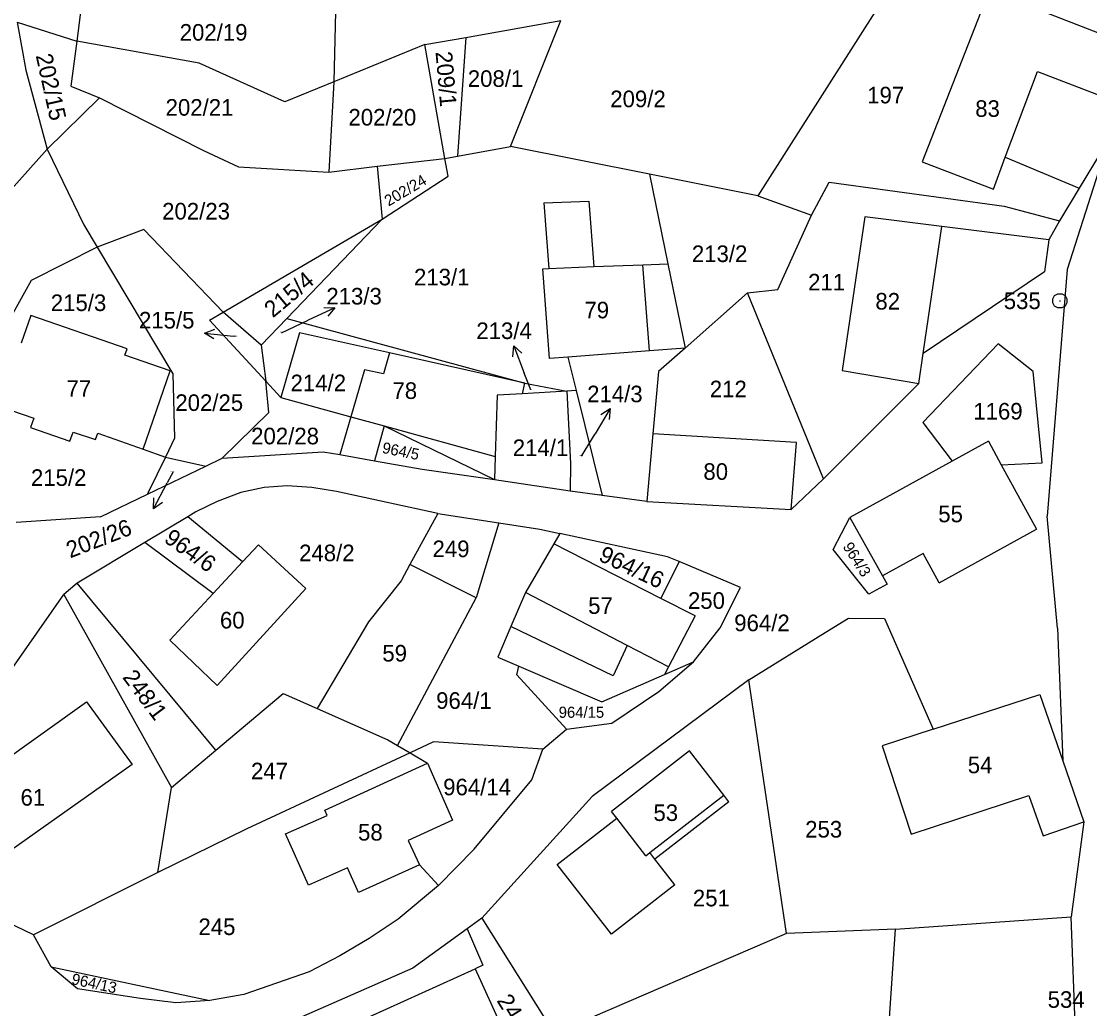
# Model space of a CAD drawing. Extents: x -593358 to -590116, y -1072518 to -1068420.
# Drawn here: x -591903.9 to -591794.4, y -1071067.8 to -1070966.6 of the extents above; entities that cross this region are included whole.
import ezdxf

# ---------------------------------------------------------------- set-up
doc = ezdxf.new("R2010")
doc.units = 0
for name, color, linetype in [('Parcela KN', 7, 'Continuous'), ('Parcela ZE', 7, 'Continuous'), ('Parcelní číslo', 7, 'Continuous'), ('Parcelní číslo_stavební', 7, 'Continuous'), ('stavby - vnitřní kresba', 7, 'Continuous'), ('Vrstva 16', 7, 'Continuous'), ('Vrstva 17', 7, 'Continuous'), ('Vrstva 24', 7, 'Continuous')]:
    doc.layers.add(name, color=color, linetype=linetype)

msp = doc.modelspace()

# ---------------------------------------------------------------- linework, layer by layer
at = {"layer": 'Parcela KN'}
for p, q in [((-591812.84, -1070959.98), (-591828.43, -1070984.45)), ((-591804.71, -1070963.4), (-591811.57, -1070980.97)), ((-591804.71, -1070963.4), (-591788.98, -1070969.54)), ((-591904.35, -1070966.66), (-591903.48, -1070971.6)), ((-591858.38, -1070968.23), (-591848.62, -1070966.51)), ((-591853.8, -1070979.4), (-591848.62, -1070966.51)), ((-591862.56, -1070968.97), (-591858.38, -1070968.23)), ((-591858.38, -1070968.23), (-591859.21, -1070980.4)), ((-591860.51, -1070980.64), (-591862.56, -1070968.97)), ((-591903.48, -1070971.6), (-591901.27, -1070979.67)), ((-591859.21, -1070980.4), (-591853.8, -1070979.4)), ((-591839.55, -1070982.24), (-591853.8, -1070979.4)), ((-591792.45, -1070978.67), (-591796.7, -1070992.01)), ((-591792.45, -1070978.67), (-591795.47, -1070983.67)), ((-591910.09, -1070989.49), (-591901.27, -1070979.67)), ((-591901.27, -1070979.67), (-591897.53, -1070987.45)), ((-591860.51, -1070980.64), (-591859.21, -1070980.4)), ((-591860.19, -1070982.46), (-591860.51, -1070980.64)), ((-591804.28, -1070983.77), (-591803.08, -1070980.5)), ((-591803.08, -1070980.5), (-591795.47, -1070983.67)), ((-591811.57, -1070980.97), (-591804.28, -1070983.77)), ((-591866.93, -1070986.84), (-591860.19, -1070982.46)), ((-591839.55, -1070982.24), (-591837.67, -1070991.42)), ((-591828.43, -1070984.45), (-591839.55, -1070982.24)), ((-591822.91, -1070986.45), (-591821.12, -1070983.06)), ((-591821.12, -1070983.06), (-591803.16, -1070985.53)), ((-591795.47, -1070983.67), (-591797.51, -1070987.04)), ((-591850.36, -1070985.18), (-591845.77, -1070985)), ((-591845.77, -1070985), (-591845.24, -1070991.72)), ((-591828.43, -1070984.45), (-591822.91, -1070986.45)), ((-591850.36, -1070985.18), (-591849.87, -1070991.91)), ((-591803.16, -1070985.53), (-591797.51, -1070987.04)), ((-591883.23, -1070996.39), (-591866.93, -1070986.84)), ((-591866.93, -1070986.84), (-591876.7, -1070997.02)), ((-591826.37, -1070994.05), (-591822.91, -1070986.45)), ((-591817.44, -1070986.63), (-591819.77, -1071002.38)), ((-591809.55, -1070987.61), (-591817.44, -1070986.63)), ((-591797.51, -1070987.04), (-591798.61, -1070988.96)), ((-591897.53, -1070987.45), (-591896.16, -1070989.74)), ((-591798.61, -1070988.96), (-591809.55, -1070987.61)), ((-591798.61, -1070988.96), (-591799.04, -1070992.25)), ((-591896.16, -1070989.74), (-591902.93, -1070993.15)), ((-591896.16, -1070989.74), (-591888.41, -1071002.71)), ((-591845.24, -1070991.72), (-591840.2, -1070991.52)), ((-591840.2, -1070991.52), (-591837.67, -1070991.42)), ((-591837.67, -1070991.42), (-591835.89, -1071000.06)), ((-591850.47, -1070991.93), (-591849.87, -1070991.91)), ((-591849.79, -1071001.14), (-591850.47, -1070991.93)), ((-591799.04, -1070992.25), (-591811.48, -1071000.63)), ((-591796.7, -1070992.01), (-591798.76, -1071017.31)), ((-591902.93, -1070993.15), (-591907.76, -1071001.82)), ((-591829.5, -1070994.41), (-591835.89, -1071000.06)), ((-591829.5, -1070994.41), (-591826.37, -1070994.05)), ((-591821.71, -1071013.46), (-591829.5, -1070994.41)), ((-591902.95, -1070996.74), (-591903.96, -1070999.56)), ((-591893.07, -1071000.16), (-591902.95, -1070996.74)), ((-591884.64, -1070997.21), (-591883.23, -1070996.39)), ((-591879.33, -1070999.76), (-591883.23, -1070996.39)), ((-591876.7, -1070997.02), (-591879.33, -1070999.76)), ((-591876.7, -1070997.02), (-591852.32, -1071003.66)), ((-591884.64, -1070997.21), (-591878.88, -1071003.46)), ((-591875.43, -1070998.51), (-591877.34, -1071005.13)), ((-591866.2, -1071000.57), (-591875.43, -1070998.51)), ((-591893.31, -1071000.81), (-591893.07, -1071000.16)), ((-591879.33, -1070999.76), (-591878.88, -1071003.46)), ((-591835.89, -1071000.06), (-591838.61, -1071002.46)), ((-591803.79, -1070999.63), (-591811.5, -1071007.69)), ((-591800.19, -1071002.48), (-591803.79, -1070999.63)), ((-591888.67, -1071002.41), (-591893.31, -1071000.81)), ((-591866.2, -1071000.57), (-591866.82, -1071002.72)), ((-591852.32, -1071003.66), (-591866.2, -1071000.57)), ((-591847.9, -1071000.99), (-591849.79, -1071001.14)), ((-591847.9, -1071000.99), (-591847.04, -1071004.43)), ((-591811.93, -1071003.68), (-591811.48, -1071000.63)), ((-591891.45, -1071010.41), (-591888.67, -1071002.41)), ((-591868.75, -1071002.29), (-591870.14, -1071007.11)), ((-591866.82, -1071002.72), (-591868.75, -1071002.29)), ((-591838.61, -1071002.46), (-591839.19, -1071008.84)), ((-591819.77, -1071002.38), (-591811.93, -1071003.68)), ((-591799.67, -1071007.7), (-591800.19, -1071002.48)), ((-591888.41, -1071002.71), (-591888.22, -1071009.29)), ((-591878.88, -1071003.46), (-591877.34, -1071005.13)), ((-591852.56, -1071004.74), (-591852.32, -1071003.66)), ((-591852.32, -1071003.66), (-591848.01, -1071004.48)), ((-591811.93, -1071003.68), (-591821.71, -1071013.46)), ((-591852.56, -1071004.74), (-591855.14, -1071004.88)), ((-591848.01, -1071004.48), (-591852.56, -1071004.74)), ((-591847.04, -1071004.43), (-591848.01, -1071004.48)), ((-591848.01, -1071004.48), (-591847.62, -1071011.9)), ((-591847.04, -1071004.43), (-591844.37, -1071015.16)), ((-591877.34, -1071005.13), (-591870.14, -1071007.11)), ((-591855.14, -1071004.88), (-591855.34, -1071011.18)), ((-591906.16, -1071006.04), (-591902.64, -1071007.25)), ((-591902.64, -1071007.25), (-591902.99, -1071008.19)), ((-591870.14, -1071007.11), (-591871.27, -1071010.99)), ((-591866.73, -1071008.05), (-591867.73, -1071011.61)), ((-591866.73, -1071008.05), (-591855.42, -1071013.55)), ((-591811.5, -1071007.69), (-591808.52, -1071011.67)), ((-591799.28, -1071011.82), (-591799.67, -1071007.7)), ((-591902.99, -1071008.19), (-591898.95, -1071009.59)), ((-591898.95, -1071009.59), (-591898.61, -1071008.67)), ((-591898.61, -1071008.67), (-591896.34, -1071009.45)), ((-591896.34, -1071009.45), (-591896.08, -1071008.77)), ((-591896.08, -1071008.77), (-591891.45, -1071010.41)), ((-591839.19, -1071008.84), (-591839.82, -1071015.79)), ((-591824.45, -1071009.73), (-591839.19, -1071008.84)), ((-591888.22, -1071009.29), (-591889.15, -1071011.23)), ((-591825, -1071016.62), (-591824.45, -1071009.73)), ((-591804.78, -1071009.62), (-591808.52, -1071011.67)), ((-591804.78, -1071009.62), (-591803.47, -1071012.02)), ((-591891.45, -1071010.41), (-591889.15, -1071011.23)), ((-591889.15, -1071011.23), (-591890.92, -1071014.88)), ((-591885.03, -1071012.17), (-591883.36, -1071011.36)), ((-591883.36, -1071011.36), (-591872.98, -1071010.69)), ((-591872.98, -1071010.69), (-591871.27, -1071010.99)), ((-591871.27, -1071010.99), (-591867.73, -1071011.61)), ((-591855.34, -1071011.18), (-591855.42, -1071013.55)), ((-591891, -1071015.04), (-591885.03, -1071012.17)), ((-591867.73, -1071011.61), (-591862.85, -1071012.47)), ((-591847.62, -1071011.9), (-591847.66, -1071014.68)), ((-591808.52, -1071011.67), (-591819.01, -1071017.43)), ((-591803.47, -1071012.02), (-591799.28, -1071011.82)), ((-591803.47, -1071012.02), (-591799.86, -1071018.63)), ((-591862.85, -1071012.47), (-591855.42, -1071013.55)), ((-591855.42, -1071013.55), (-591847.66, -1071014.68)), ((-591825, -1071016.62), (-591821.71, -1071013.46)), ((-591879.03, -1071014.37), (-591881.42, -1071014.87)), ((-591876.69, -1071014.2), (-591879.03, -1071014.37)), ((-591874.16, -1071014.34), (-591876.69, -1071014.2)), ((-591871.61, -1071014.75), (-591874.16, -1071014.34)), ((-591895.82, -1071017.36), (-591891, -1071015.04)), ((-591890.92, -1071014.88), (-591891, -1071015.04)), ((-591881.42, -1071014.87), (-591883.86, -1071015.78)), ((-591861.24, -1071017.03), (-591871.61, -1071014.75)), ((-591847.66, -1071014.68), (-591844.64, -1071015.12)), ((-591844.37, -1071015.16), (-591844.64, -1071015.12)), ((-591839.82, -1071015.79), (-591844.37, -1071015.16)), ((-591883.86, -1071015.78), (-591886.06, -1071016.86)), ((-591839.82, -1071015.79), (-591825, -1071016.62)), ((-591895.82, -1071017.36), (-591904.48, -1071017.94)), ((-591886.87, -1071017.35), (-591891.27, -1071019.99)), ((-591886.06, -1071016.86), (-591886.87, -1071017.35)), ((-591881.25, -1071021.98), (-591886.87, -1071017.35)), ((-591861.24, -1071017.03), (-591864.1, -1071022.24)), ((-591861.24, -1071017.03), (-591854.99, -1071017.99)), ((-591820.71, -1071020.71), (-591819.01, -1071017.43)), ((-591819.01, -1071017.43), (-591815.65, -1071023.42)), ((-591797.69, -1071028.77), (-591798.76, -1071017.31)), ((-591854.99, -1071017.99), (-591857.3, -1071025.66)), ((-591854.99, -1071017.99), (-591850.78, -1071018.64)), ((-591850.78, -1071018.64), (-591848.72, -1071019.06)), ((-591809.85, -1071024.12), (-591799.86, -1071018.63)), ((-591891.27, -1071019.99), (-591898.22, -1071024.15)), ((-591884.28, -1071025.23), (-591891.27, -1071019.99)), ((-591848.72, -1071019.06), (-591849.35, -1071020.14)), ((-591837.7, -1071021.45), (-591848.72, -1071019.06)), ((-591881.25, -1071021.98), (-591879.62, -1071020.22)), ((-591879.62, -1071020.22), (-591874.77, -1071024.72)), ((-591849.35, -1071020.14), (-591852.25, -1071025.12)), ((-591838.38, -1071025.72), (-591849.35, -1071020.14)), ((-591817.03, -1071025.27), (-591820.71, -1071020.71)), ((-591811.49, -1071021.13), (-591815.65, -1071023.42)), ((-591809.85, -1071024.12), (-591811.49, -1071021.13)), ((-591884.28, -1071025.23), (-591881.25, -1071021.98)), ((-591864.1, -1071022.24), (-591864.99, -1071023.91)), ((-591857.3, -1071025.66), (-591864.1, -1071022.24)), ((-591836.49, -1071021.95), (-591838.38, -1071025.72)), ((-591836.49, -1071021.95), (-591837.7, -1071021.45)), ((-591830.19, -1071024.6), (-591836.49, -1071021.95)), ((-591898.22, -1071024.15), (-591899.57, -1071025.31)), ((-591883.98, -1071041.28), (-591898.22, -1071024.15)), ((-591864.99, -1071023.91), (-591868.33, -1071028.11)), ((-591815.18, -1071024.26), (-591817.03, -1071025.27)), ((-591815.65, -1071023.42), (-591815.18, -1071024.26)), ((-591913.18, -1071044.74), (-591899.57, -1071025.31)), ((-591899.57, -1071025.31), (-591888.53, -1071045.1)), ((-591888.72, -1071030), (-591884.28, -1071025.23)), ((-591874.77, -1071024.72), (-591883.86, -1071034.64)), ((-591852.25, -1071025.12), (-591853.74, -1071028.61)), ((-591832.29, -1071028.73), (-591830.19, -1071024.6)), ((-591865.38, -1071040.78), (-591857.3, -1071025.66)), ((-591834.85, -1071027.52), (-591838.38, -1071025.72)), ((-591834.85, -1071027.52), (-591837.59, -1071032.73)), ((-591821.54, -1071029.21), (-591819.12, -1071027.75)), ((-591819.12, -1071027.75), (-591815.45, -1071027.77)), ((-591815.45, -1071027.77), (-591810.44, -1071039.11)), ((-591868.33, -1071028.11), (-591873.6, -1071037)), ((-591853.74, -1071028.61), (-591855.08, -1071031.76)), ((-591835.01, -1071032.21), (-591832.29, -1071028.73)), ((-591797.69, -1071028.77), (-591797.16, -1071042.38)), ((-591829.35, -1071034.05), (-591821.54, -1071029.21)), ((-591883.86, -1071034.64), (-591888.72, -1071030)), ((-591855.08, -1071031.76), (-591852.92, -1071032.68)), ((-591853.15, -1071033.54), (-591852.92, -1071032.68)), ((-591852.92, -1071032.68), (-591844.42, -1071036.31)), ((-591838.58, -1071035.25), (-591835.01, -1071032.21)), ((-591838, -1071033.51), (-591835.01, -1071032.21)), ((-591837.59, -1071032.73), (-591838, -1071033.51)), ((-591848.05, -1071039.12), (-591853.15, -1071033.54)), ((-591829.35, -1071034.05), (-591845.4, -1071046.01)), ((-591844.42, -1071036.31), (-591838, -1071033.51)), ((-591825.5, -1071060.05), (-591829.35, -1071034.05)), ((-591843.4, -1071038.5), (-591838.58, -1071035.25)), ((-591883.98, -1071041.28), (-591877.08, -1071035.47)), ((-591877.08, -1071035.47), (-591873.6, -1071037)), ((-591810.44, -1071039.11), (-591799.52, -1071035.58)), ((-591799.52, -1071035.58), (-591797.16, -1071042.38)), ((-591873.6, -1071037), (-591866.37, -1071040.2)), ((-591848.05, -1071039.12), (-591843.4, -1071038.5)), ((-591850.47, -1071041.18), (-591848.05, -1071039.12)), ((-591810.44, -1071039.11), (-591815.69, -1071040.83)), ((-591866.37, -1071040.2), (-591865.38, -1071040.78)), ((-591865.38, -1071040.78), (-591864.08, -1071041.55)), ((-591861.68, -1071040.43), (-591864.08, -1071041.55)), ((-591850.47, -1071041.18), (-591861.68, -1071040.43)), ((-591815.69, -1071040.83), (-591812.72, -1071049.88)), ((-591888.53, -1071045.1), (-591883.98, -1071041.28)), ((-591864.08, -1071041.55), (-591880.82, -1071049.34)), ((-591864.08, -1071041.55), (-591862.29, -1071042.6)), ((-591851.58, -1071044.33), (-591850.47, -1071041.18)), ((-591835.43, -1071041.34), (-591843.43, -1071047.55)), ((-591831.91, -1071045.89), (-591835.43, -1071041.34)), ((-591872.83, -1071047.42), (-591862.29, -1071042.6)), ((-591862.29, -1071042.6), (-591859.72, -1071048.45)), ((-591797.16, -1071042.38), (-591795, -1071048.61)), ((-591889.93, -1071053.8), (-591888.53, -1071045.1)), ((-591857.51, -1071051.43), (-591851.58, -1071044.33)), ((-591845.4, -1071046.01), (-591856.73, -1071058.48)), ((-591831.39, -1071046.56), (-591831.91, -1071045.89)), ((-591812.72, -1071049.88), (-591800.64, -1071045.91)), ((-591800.64, -1071045.91), (-591799.19, -1071050.07)), ((-591872.58, -1071047.96), (-591872.83, -1071047.42)), ((-591831.39, -1071046.56), (-591838.98, -1071052.43)), ((-591876.86, -1071049.86), (-591872.58, -1071047.96)), ((-591859.72, -1071048.45), (-591864.26, -1071050.53)), ((-591848.99, -1071052.98), (-591842.88, -1071048.26)), ((-591842.88, -1071048.26), (-591843.43, -1071047.55)), ((-591880.82, -1071049.34), (-591889.93, -1071053.8)), ((-591799.19, -1071050.07), (-591795, -1071048.61)), ((-591795, -1071048.61), (-591796.32, -1071058.37)), ((-591874.5, -1071055.11), (-591876.86, -1071049.86)), ((-591864.26, -1071050.53), (-591863.12, -1071053.02)), ((-591861.15, -1071055.15), (-591857.51, -1071051.43)), ((-591843.42, -1071060.13), (-591848.99, -1071052.98)), ((-591836.92, -1071055.09), (-591838.98, -1071052.43)), ((-591889.93, -1071053.8), (-591902.69, -1071060.19)), ((-591870.48, -1071053.33), (-591874.5, -1071055.11)), ((-591869.38, -1071055.87), (-591870.48, -1071053.33)), ((-591863.12, -1071053.02), (-591869.38, -1071055.87)), ((-591863.12, -1071053.02), (-591861.15, -1071055.15)), ((-591861.15, -1071055.15), (-591865.29, -1071058.59)), ((-591836.92, -1071055.09), (-591843.42, -1071060.13)), ((-591902.69, -1071060.19), (-591909.37, -1071057)), ((-591814.32, -1071059.63), (-591796.32, -1071058.37)), ((-591795.58, -1071076.73), (-591796.32, -1071058.37)), ((-591865.29, -1071058.59), (-591868.26, -1071060.58)), ((-591856.73, -1071058.48), (-591858.23, -1071059.59)), ((-591856.73, -1071058.48), (-591849.3, -1071070.31)), ((-591900.89, -1071063.47), (-591902.69, -1071060.19)), ((-591868.26, -1071060.58), (-591871.28, -1071062.35)), ((-591858.23, -1071059.59), (-591863.81, -1071063.62)), ((-591858.23, -1071059.59), (-591856.62, -1071063.3)), ((-591825.5, -1071060.05), (-591849.3, -1071070.31)), ((-591814.32, -1071059.63), (-591825.5, -1071060.05)), ((-591815.08, -1071070.77), (-591814.32, -1071059.63)), ((-591871.28, -1071062.35), (-591874.44, -1071063.99)), ((-591898.18, -1071065.75), (-591900.89, -1071063.47)), ((-591900.89, -1071063.47), (-591884.6, -1071066.93)), ((-591863.81, -1071063.62), (-591882.32, -1071071.72)), ((-591856.62, -1071063.3), (-591857.42, -1071063.67)), ((-591857.42, -1071063.67), (-591854.58, -1071069.9)), ((-591874.44, -1071063.99), (-591881.13, -1071066.31)), ((-591891.7, -1071066.72), (-591898.18, -1071065.75)), ((-591888.08, -1071067.17), (-591891.7, -1071066.72)), ((-591884.6, -1071066.93), (-591888.08, -1071067.17)), ((-591881.13, -1071066.31), (-591884.6, -1071066.93))]:
    msp.add_line(p, q, dxfattribs=at)
at = {"layer": 'Parcela ZE'}
for p, q in [((-591871.66, -1070962.43), (-591871.88, -1070972.78)), ((-591897.82, -1070965.36), (-591898.25, -1070968.61)), ((-591904.35, -1070966.66), (-591898.25, -1070968.61)), ((-591898.25, -1070968.61), (-591898.87, -1070973.23)), ((-591885.69, -1070970.88), (-591898.25, -1070968.61)), ((-591862.56, -1070968.97), (-591871.88, -1070972.78)), ((-591876.91, -1070974.84), (-591885.69, -1070970.88)), ((-591871.88, -1070972.78), (-591876.91, -1070974.84)), ((-591871.88, -1070972.78), (-591872.41, -1070982.04)), ((-591898.87, -1070973.23), (-591895.91, -1070974.43)), ((-591901.27, -1070979.67), (-591895.91, -1070974.43)), ((-591895.91, -1070974.43), (-591885.26, -1070979.81)), ((-591885.26, -1070979.81), (-591881.67, -1070981.5)), ((-591867.47, -1070981.44), (-591860.51, -1070980.64)), ((-591881.67, -1070981.5), (-591872.41, -1070982.04)), ((-591872.41, -1070982.04), (-591867.47, -1070981.44)), ((-591867.47, -1070981.44), (-591866.93, -1070986.84)), ((-591891.37, -1070987.9), (-591896.16, -1070989.74)), ((-591883.23, -1070996.39), (-591891.37, -1070987.9)), ((-591878.57, -1071006.68), (-591878.88, -1071003.46)), ((-591883.36, -1071011.36), (-591878.57, -1071006.68)), ((-591889.15, -1071011.23), (-591885.03, -1071012.17))]:
    msp.add_line(p, q, dxfattribs=at)
at = {"layer": 'stavby - vnitřní kresba'}
for p, q in [((-591803.08, -1070980.5), (-591799.76, -1070971.71)), ((-591799.76, -1070971.71), (-591791.08, -1070975.08)), ((-591811.48, -1071000.63), (-591809.55, -1070987.61)), ((-591839.54, -1071000.34), (-591840.2, -1070991.52)), ((-591849.87, -1070991.91), (-591845.24, -1070991.72)), ((-591839.54, -1071000.34), (-591847.9, -1071000.99)), ((-591835.89, -1071000.06), (-591839.54, -1071000.34)), ((-591870.14, -1071007.11), (-591866.73, -1071008.05)), ((-591866.73, -1071008.05), (-591855.34, -1071011.18)), ((-591841.81, -1071030.54), (-591852.25, -1071025.12)), ((-591843.25, -1071033.65), (-591853.74, -1071028.61)), ((-591841.81, -1071030.54), (-591843.25, -1071033.65)), ((-591837.59, -1071032.73), (-591841.81, -1071030.54)), ((-591912.47, -1071047.2), (-591897.24, -1071036.32)), ((-591897.24, -1071036.32), (-591892.58, -1071042.73)), ((-591892.58, -1071042.73), (-591907.41, -1071053.23)), ((-591839.49, -1071051.77), (-591831.91, -1071045.89)), ((-591839.92, -1071052.1), (-591842.88, -1071048.26)), ((-591839.92, -1071052.1), (-591839.49, -1071051.77)), ((-591838.98, -1071052.43), (-591839.49, -1071051.77)), ((-591872.58, -1071070.53), (-591857.42, -1071063.67))]:
    msp.add_line(p, q, dxfattribs=at)
at = {"layer": 'Vrstva 16'}
for p, q in [((-591871.808, -1070995.928), (-591874.52, -1070997.21)), ((-591877.25, -1070998.5), (-591874.52, -1070997.21)), ((-591885.153, -1070998.527), (-591882.17, -1070998.85)), ((-591881.91, -1070998.88), (-591882.17, -1070998.85)), ((-591853.446, -1070999.84), (-591852.37, -1071002.64)), ((-591851.71, -1071004.36), (-591852.37, -1071002.64)), ((-591843.575, -1071006.269), (-591845.12, -1071008.84)), ((-591846.5, -1071011.13), (-591845.12, -1071008.84)), ((-591888.38, -1071012.75), (-591888.98, -1071013.88)), ((-591890.375, -1071016.536), (-591888.98, -1071013.88))]:
    msp.add_line(p, q, dxfattribs=at)
for points in [[(-591872.926, -1070995.903), (-591871.808, -1070995.928), (-591872.498, -1070996.807)], [(-591884.212, -1070999.132), (-591885.153, -1070998.527), (-591884.105, -1070998.138)], [(-591853.554, -1071000.953), (-591853.446, -1070999.84), (-591852.621, -1071000.594)], [(-591844.518, -1071006.868), (-591843.575, -1071006.269), (-591843.661, -1071007.383)], [(-591889.467, -1071015.883), (-591890.375, -1071016.536), (-591890.353, -1071015.418)]]:
    msp.add_lwpolyline(points, dxfattribs=at)
at = {"layer": 'Vrstva 24'}
msp.add_line((-591797.51, -1070995.22), (-591797.41, -1070995.22), dxfattribs=at)
msp.add_lwpolyline([(-591797.27, -1070994.5), (-591796.93, -1070994.69), (-591796.74, -1070995.03), (-591796.74, -1070995.42), (-591796.93, -1070995.76), (-591797.27, -1070995.95), (-591797.66, -1070995.95), (-591798, -1070995.76), (-591798.19, -1070995.42), (-591798.19, -1070995.03), (-591798, -1070994.69), (-591797.66, -1070994.5)], close=True, dxfattribs=at)

# ---------------------------------------------------------------- texts
at = {"layer": 'Parcelní číslo'}
for s, height, p in [('202/19', 1.7, (-591887.698, -1070968.56)), ('208/1', 1.7, (-591858.162, -1070973.3)), ('209/2', 1.7, (-591843.557, -1070975.38)), ('197', 1.7, (-591817.216, -1070974.99)), ('202/21', 1.7, (-591889.142, -1070976.25)), ('202/20', 1.7, (-591870.397, -1070977.26)), ('202/23', 1.7, (-591889.497, -1070986.89)), ('213/2', 1.7, (-591835.189, -1070991.25)), ('213/1', 1.7, (-591863.678, -1070993.64)), ('211', 1.7, (-591823.272, -1070994.16)), ('215/3', 1.7, (-591900.913, -1070996.27)), ('215/5', 0.1, (-591882.101, -1070998.88)), ('213/3', 0.1, (-591877.446, -1070998.5)), ('214/2', 1.7, (-591876.332, -1071004.49)), ('212', 1.7, (-591833.353, -1071005.11)), ('202/25', 1.7, (-591888.147, -1071006.51)), ('213/4', 0.1, (-591851.901, -1071004.36)), ('1169', 1.7, (-591806.337, -1071007.39)), ('202/28', 1.7, (-591880.37, -1071009.93)), ('214/1', 1.7, (-591853.551, -1071011.13)), ('214/3', 0.1, (-591846.691, -1071011.13)), ('215/2', 1.7, (-591902.949, -1071014.19)), ('202/26', 0.1, (-591888.637, -1071012.75)), ('248/2', 1.7, (-591875.457, -1071021.91)), ('249', 1.7, (-591861.778, -1071021.49)), ('250', 1.7, (-591835.591, -1071026.79)), ('964/2', 1.7, (-591830.847, -1071029.08)), ('964/1', 1.7, (-591861.405, -1071037.04)), ('964/15', 1.14, (-591848.842, -1071037.96)), ('247', 1.7, (-591880.388, -1071044.26)), ('964/14', 1.7, (-591860.684, -1071045.9)), ('253', 1.7, (-591823.572, -1071050.23)), ('251', 1.7, (-591835.087, -1071057.28)), ('245', 1.7, (-591885.775, -1071060.22))]:
    msp.add_text(s, height=height, dxfattribs=at).set_placement(p)
for s, height, rotation, p in [('209/1', 1.7, 274.90515, (-591861.472, -1070969.726)), ('202/15', 1.7, 282.52549, (-591902.466, -1070970.09)), ('202/24', 1.14, 30.65324, (-591866.281, -1070985.574)), ('215/4', 1.7, 39.76327, (-591878.144, -1070997.03)), ('964/5', 1.14, 348.75941, (-591867.009, -1071010.805)), ('964/6', 1.7, 324.75248, (-591889.414, -1071019.859)), ('964/3', 1.14, 302.34983, (-591819.763, -1071020.416)), ('964/16', 1.7, 334.83654, (-591844.856, -1071021.805)), ('248/1', 1.7, 306.87619, (-591893.632, -1071033.822)), ('964/13', 1.14, 348.01456, (-591898.853, -1071065.242)), ('244', 1.7, 302.12064, (-591855.248, -1071066.943))]:
    msp.add_text(s, height=height, rotation=rotation, dxfattribs=at).set_placement(p)
at = {"layer": 'Parcelní číslo_stavební'}
for s, p in [('83', (-591806.139, -1070976.37)), ('82', (-591816.375, -1070996.12)), ('79', (-591846.205, -1070997.02)), ('77', (-591899.295, -1071005.06)), ('78', (-591865.885, -1071005.28)), ('80', (-591834.008, -1071013.57)), ('55', (-591809.929, -1071017.92)), ('57', (-591845.822, -1071027.31)), ('60', (-591883.572, -1071028.8)), ('59', (-591866.922, -1071032.19)), ('54', (-591806.902, -1071043.64)), ('61', (-591904.017, -1071046.96)), ('53', (-591839.129, -1071048.53)), ('58', (-591869.412, -1071050.54))]:
    msp.add_text(s, height=1.7, dxfattribs=at).set_placement(p)
at = {"layer": 'Vrstva 16'}
for s, p in [('213/3', (-591872.663, -1070995.6)), ('215/5', (-591891.873, -1070998.06)), ('213/4', (-591857.286, -1070999.14)), ('214/3', (-591845.926, -1071005.62))]:
    msp.add_text(s, height=1.7, dxfattribs=at).set_placement(p)
msp.add_text('202/26', height=1.7, rotation=21.14214, dxfattribs=at).set_placement((-591898.931, -1071021.624))
at = {"layer": 'Vrstva 17'}
for s, p in [('535', (-591803.214, -1070996.07)), ('534', (-591798.714, -1071067.68))]:
    msp.add_text(s, height=1.7, dxfattribs=at).set_placement(p)

doc.saveas('drawing.dxf')
